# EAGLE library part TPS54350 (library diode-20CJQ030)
TI's TPS54350 4.5V to 20V input 3Amp output buck stepdown switcher with integrated highside 100mOhm fet and optional lowside synchronous rectifier gate drive or diode. 250kHz to 700kHz fixed or adjustable PWM frequency Internal current and thermal protection 16 pin TSSOP PowerPAD package (central pad is ground) DESCRIPTION The TPS54350 is a medium output current synchronous buck PWM converter with an integrated high side MOSFET and a gate driver for an optional low side external MOSFET. Features include a high performance voltage error amplifier that enables maximum performance under transient conditions and flexibility in choosing the output filter inductors and capacitors. The TPS54350 has an under-voltage-lockout circuit to prevent start-up until the input voltage reaches 4.5 V; an internal slow-start circuit to limit in-rush currents; and a power good output to indicate valid output conditions. The synchronization feature is configurable as either an input or an output for easy 180° out of phase synchronization. The TPS54350 device is available in a thermally enhanced 16-pin TSSOP (PWP) PowerPAD? package. TI provides evaluation modules and the SWIFT? Designer software tool to aid in quickly achieving high-performance power supply designs to meet aggressive equipment development cycles. FEATURES 100 m?, 4.5-A Peak MOSFET Switch for High Efficiency at 3-A Continuous Output Current Uses External Lowside MOSFET or Diode Output Voltage Adjustable Down to 0.891 V With 1%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
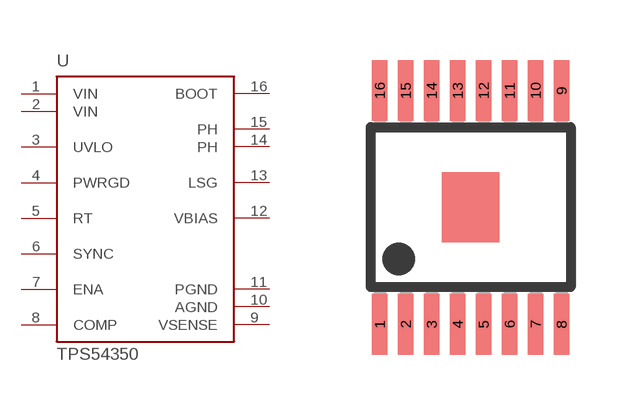
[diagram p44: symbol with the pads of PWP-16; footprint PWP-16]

Designator prefix U

## TPS54350  [PWP-16]
1  VIN  pwr
2  VIN  pwr
3  UVLO  in
4  PWRGD  out
5  RT  in
6  SYNC
7  ENA  in
8  COMP  out
9  VSENSE  in
10  AGND  pwr
11  PGND  pwr
12  VBIAS  pas
13  LSG  out
14  PH  out
15  PH  out
16  BOOT  pas

## Footprint PWP-16 (pad centres in mm)
TI TPS54350 buck stepdown 3Amp switcher 16 pin TSSOP PowerPAD package (central pad is ground)
smd 0.381 x 1.524: 1 -2.275,-2.925; 2 -1.625,-2.925; 3 -0.975,-2.925; 4 -0.325,-2.925; 5 0.325,-2.925; 6 0.975,-2.925; 7 1.625,-2.925; 8 2.275,-2.925; 9 2.275,2.917; 10 1.625,2.917; 11 0.975,2.917; 12 0.325,2.917; 13 -0.325,2.917; 14 -0.975,2.917; 15 -1.625,2.917; 16 -2.275,2.917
